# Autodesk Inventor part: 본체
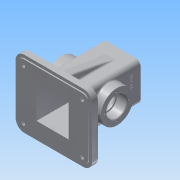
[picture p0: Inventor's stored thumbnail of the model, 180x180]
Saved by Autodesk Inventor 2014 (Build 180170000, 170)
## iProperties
Created: 2015-12
Part Number: 본체
Material: 알루미늄 6061
Document SubType Name: Modeling
Designer: Administrator
Density: 2.71 g/cm^3
Appearance: 알루미늄 - 평지
Author: Administrator
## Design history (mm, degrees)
sketch "스케치1"
  geometry: L1 (32.5, 55)-(-32.5, 55); L2 (-32.5, 55)-(-32.5, -55); L3 (-32.5, -55)-(32.5, -55); L4 (32.5, -55)-(32.5, 55); L5 (32.5, 55)-(-32.5, -55); L6 (-32.5, 55)-(32.5, -55); 1 further point
  constraints: 12 end point, 2 midpoint, 2 parallel, 1 horizontal, 1 perpendicular
  dimensions: "d0" = 65 distance of L3.end L2.end; "d1" = 110 distance of L2.end L1.end
extrude "돌출1" new body sketch "스케치1" stored distance "d2" = 65; taper "d3" = 0 deg
sketch "스케치2"
  geometry: C1 r 20 at (32.5, 32.5); 1 further point
  constraints: 1 centre point, 1 coincident
  dimensions: "d4" = 40 diameter of C1
extrude "돌출2" join sketch "스케치2" distance "d5" = 10; taper "d6" = 0 deg
sketch "스케치3"
  geometry: L1 (50, 27.5)-(-55, 27.5); L2 (-55, 27.5)-(-55, -27.5); L3 (-55, -27.5)-(50, -27.5); L4 (50, -27.5)-(50, 27.5); L5 (-55, -32.5)-(-55, 32.5) reference; 3 further points
  constraints: 8 end point, 3 midpoint, 2 parallel, 1 horizontal, 1 horizontal alignment, 1 perpendicular
  dimensions: "d9" = 105 distance of L3.end L2.end; "d10" = 55 distance of L2.end L1.end
extrude "돌출3" cut sketch "스케치3" stored distance "d11" = 55; taper "d12" = 0 deg
sketch "스케치4"
  geometry: C1 r 20 at (0, 0) reference; C2 r 10.5 at (0, 0)
  constraints: 1 centre point, 1 coincident
  dimensions: "d13" = 21 diameter of C2
extrude "돌출4" cut sketch "스케치4" stored distance "d14" = 55; taper "d15" = 0 deg
sketch "스케치5"
  geometry: C1 r 27.5 at (-32.5, 55); 1 further point
  constraints: 1 centre point, 1 coincident
  dimensions: "d16" = 55 diameter of C1
extrude "돌출5" join sketch "스케치5" distance "d17" = 15; taper "d18" = 0 deg
sketch "스케치6" dims "d19" = 42
  geometry: C1 r 27.5 at (0, 0) reference; 2 further points
  constraints: 1 coincident, 1 vertical alignment, 2 other
hole "구멍1" sketch "스케치6" at (0, 21) diameter "d20" = 3.242; stored, may be unused: countersink angle "d24" = 90 deg, drill point angle "d26" = 118 deg; dims "d21" = 8, "d22" = 4, "d23" = 2, "d25" = 10
sketch "스케치7"
  geometry: C1 r 27.5 at (0, 0) reference; C2 r 17.5 at (0, 0)
  constraints: 1 centre point, 1 coincident
  dimensions: "d30" = 35 diameter of C2
extrude "돌출6" cut sketch "스케치7" distance "d31" = 17; taper "d32" = 0 deg
sketch "스케치8"
  geometry: C1 r 17.5 at (0, 0) reference; C2 r 15 at (0, 0)
  constraints: 1 centre point, 1 coincident
  dimensions: "d33" = 30 diameter of C2
extrude "돌출7" cut sketch "스케치8" stored distance "d34" = 17; taper "d35" = 0 deg
sketch "스케치11" dims "d36" = 29
  geometry: C1 r 20 at (0, 0) reference; 2 further points
  constraints: 1 coincident, 1 vertical alignment, 2 other
hole "구멍2" sketch "스케치11" at (0, 14.5) diameter "d37" = 2.459; stored, may be unused: countersink angle "d41" = 90 deg, drill point angle "d43" = 118 deg; dims "d38" = 8, "d39" = 4, "d40" = 2, "d42" = 10
node "작업 평면1"
sketch "스케치14"
  geometry: L1 (-65, 57.5)-(65, 57.5); L2 (65, 57.5)-(65, -57.5); L3 (65, -57.5)-(-65, -57.5); L4 (-65, -57.5)-(-65, 57.5); L5 (-65, 57.5)-(65, -57.5); L6 (65, 57.5)-(-65, -57.5); 1 further point
  constraints: 12 end point, 2 midpoint, 2 parallel, 1 horizontal, 1 perpendicular
  dimensions: "d50" = 130 distance of L2.end L3.end; "d51" = 115 distance of L1.end L2.end
extrude "돌출8" join sketch "스케치14" distance "d52" = 10; taper "d53" = 0 deg
sketch "스케치15"
  geometry: L1 (60, 52.5)-(-60, 52.5); L2 (-60, 52.5)-(-60, -52.5); L3 (-60, -52.5)-(60, -52.5); L4 (60, -52.5)-(60, 52.5); L5 (60, 52.5)-(-60, -52.5); L6 (-60, 52.5)-(60, -52.5); 1 further point
  constraints: 12 end point, 2 midpoint, 2 parallel, 1 horizontal, 1 perpendicular
  dimensions: "d54" = 120 distance of L3.end L2.end; "d55" = 105 distance of L2.end L1.end
extrude "돌출9" join sketch "스케치15" distance "d56" = 2; taper "d57" = 0 deg
fillet "모깎기1" dims "d59" = 15
sketch "스케치17"
  geometry: C1 r 7.5 at (-50, 42.5); C2 r 7.5 at (50, 42.5); C3 r 7.5 at (-50, -42.5); C4 r 7.5 at (50, -42.5); A1 r 15 centre (-50, 42.5) between (-50, 57.5) and (-65, 42.5) reference; A2 r 15 centre (-50, -42.5) between (-65, -42.5) and (-50, -57.5) reference; A3 r 15 centre (50, -42.5) between (50, -57.5) and (65, -42.5) reference; A4 r 15 centre (50, 42.5) between (65, 42.5) and (50, 57.5) reference; 1 further point
  constraints: 4 centre point, 4 coincident
  dimensions: "d60" = 15 diameter of C1; "d61" = 15 diameter of C2; "d62" = 15 diameter of C3; "d63" = 15 diameter of C4
extrude "돌출10" join sketch "스케치17" distance "d64" = 3; taper "d65" = 0 deg
sketch "스케치18"
  geometry: C1 r 7.5 at (0, 0) reference; C2 r 3 at (0, 0); 1 further point
  constraints: 1 centre point, 1 coincident
  dimensions: "d66" = 6 diameter of C2
extrude "돌출11" cut sketch "스케치18" stored distance "d67" = 3; taper "d68" = 0 deg
sketch "스케치19"
  geometry: C1 r 7.5 at (0, 0) reference; C2 r 3 at (0, 0); 1 further point
  constraints: 1 centre point, 1 coincident
  dimensions: "d69" = 6 diameter of C2
extrude "돌출12" cut sketch "스케치19" stored distance "d70" = 3; taper "d71" = 0 deg
sketch "스케치21"
  geometry: L1 (65, -20)-(55, -20) reference; L2 (55, -20)-(55, -32.5) reference; L3 (55, -32.5)-(-50, -32.5) reference; L4 (-50, -32.5)-(-50, -57.5) reference; L5 (-50, -57.5)-(-60, -57.5) reference; L6 (-60, -57.5)-(-60, -52.5) reference; L7 (-60, -52.5)-(-62, -52.5) reference; L8 (-62, -52.5)-(-62, 52.5) reference; L9 (-62, 52.5)-(-60, 52.5) reference; L10 (-60, 52.5)-(-60, 57.5) reference; L11 (-60, 57.5)-(-50, 57.5) reference; L12 (-50, 57.5)-(-50, 32.5) reference; L13 (-50, 32.5)-(55, 32.5) reference; L14 (55, 32.5)-(55, 20) reference; L15 (55, 20)-(65, 20) reference; L16 (65, 20)-(65, 15.73) reference; L17 (65, 15.73)-(55, 15.73) reference; L18 (55, 15.73)-(54.261, 14.5) reference; L19 (54.261, 14.5)-(55, 13.271) reference; L20 (55, 13.271)-(65, 13.271) reference; L21 (65, 13.271)-(65, 10.5) reference; L22 (65, 10.5)-(50, 10.5) reference; L23 (50, 10.5)-(50, 27.5) reference; L24 (50, 27.5)-(-50, 27.5) reference; L25 (-50, 27.5)-(-50, -27.5) reference; L26 (-50, -27.5)-(50, -27.5) reference; L27 (50, -27.5)-(50, -10.5) reference; L28 (50, -10.5)-(65, -10.5) reference; L29 (65, -10.5)-(65, -13.271) reference; L30 (65, -13.271)-(55, -13.271) reference; L31 (55, -13.271)-(54.261, -14.5) reference; L32 (54.261, -14.5)-(55, -15.73) reference; L33 (55, -15.73)-(65, -15.73) reference; L34 (65, -15.73)-(65, -20) reference; L35 (-50, 57.5)-(-50, 47.5); L36 (-50, 47.5)-(35.069, 32.5); 1 further point
  constraints: 4 end point, 2 point on line
  dimensions: "d77" = 10 distance of L11.end L35.end; "d78" = 80 deg angle of L12 L36
extrude "돌출13" join sketch "스케치21" stored distance "d79" = 15; taper "d80" = 0 deg
fillet "모깎기2" dims "d81" = 10
sketch "스케치22"
  geometry: L1 (-37.5, -22.621)-(-36.526, -21) reference; L2 (-36.526, -21)-(-37.5, -19.379) reference; L3 (-37.5, -19.379)-(-47.5, -19.379) reference; L4 (-47.5, -19.379)-(-47.5, -17.5) reference; L5 (-47.5, -17.5)-(-30.5, -17.5) reference; L6 (-30.5, -17.5)-(-30.5, -15) reference; L7 (-30.5, -15)-(-27.5, -15) reference; L8 (-27.5, -15)-(-27.5, -50) reference; L9 (-27.5, -50)-(27.5, -50) reference; L10 (27.5, -50)-(27.5, -15) reference; L11 (27.5, -15)-(30.5, -15) reference; L12 (30.5, -15)-(30.5, -17.5) reference; L13 (30.5, -17.5)-(47.5, -17.5) reference; L14 (47.5, -17.5)-(47.5, -19.379) reference; L15 (47.5, -19.379)-(37.5, -19.379) reference; L16 (37.5, -19.379)-(36.526, -21) reference; L17 (36.526, -21)-(37.5, -22.621) reference; L18 (37.5, -22.621)-(47.5, -22.621) reference; L19 (47.5, -22.621)-(47.5, -27.5) reference; L20 (47.5, -27.5)-(32.5, -27.5) reference; L21 (32.5, -27.5)-(32.5, -50) reference; L22 (32.5, -50)-(65, -50) reference; L23 (65, -50)-(65, -60) reference; L24 (65, -60)-(60, -60) reference; L25 (60, -60)-(60, -62) reference; L26 (60, -62)-(-60, -62) reference; L27 (-60, -62)-(-60, -60) reference; L28 (-60, -60)-(-65, -60) reference; L29 (-65, -60)-(-65, -50) reference; L30 (-65, -50)-(-32.5, -50) reference; L31 (-32.5, -50)-(-32.5, -27.5) reference; L32 (-32.5, -27.5)-(-47.5, -27.5) reference; L33 (-47.5, -27.5)-(-47.5, -22.621) reference; L34 (-47.5, -22.621)-(-37.5, -22.621) reference; L35 (-20, 55)-(-20, 65) reference; L36 (-20, 65)-(-15.729, 65) reference; L37 (-15.729, 65)-(-15.729, 55) reference; L38 (-15.729, 55)-(-14.5, 54.261) reference; L39 (-14.5, 54.261)-(-13.27, 55) reference; L40 (-13.27, 55)-(-13.27, 65) reference; L41 (-13.27, 65)-(-10.5, 65) reference; L42 (-10.5, 65)-(-10.5, 50) reference; L43 (-10.5, 50)-(-27.5, 50) reference; L44 (-27.5, 50)-(-27.5, 15) reference; L45 (-27.5, 15)-(-30.5, 15) reference; L46 (-30.5, 15)-(-30.5, 17.5) reference; L47 (-30.5, 17.5)-(-47.5, 17.5) reference; L48 (-47.5, 17.5)-(-47.5, 19.379) reference; L49 (-47.5, 19.379)-(-37.5, 19.379) reference; L50 (-37.5, 19.379)-(-36.526, 21) reference; L51 (-36.526, 21)-(-37.5, 22.621) reference; L52 (-37.5, 22.621)-(-47.5, 22.621) reference; L53 (-47.5, 22.621)-(-47.5, 27.5) reference; L54 (-47.5, 27.5)-(-32.5, 27.5) reference; L55 (-32.5, 27.5)-(-32.5, 55) reference; L56 (-32.5, 55)-(-20, 55) reference; L57 (20, 65)-(20, 55) reference; L58 (20, 55)-(32.5, 55) reference; L59 (32.5, 55)-(32.5, 27.5) reference; L60 (32.5, 27.5)-(47.5, 27.5) reference; L61 (47.5, 27.5)-(47.5, 22.621) reference; L62 (47.5, 22.621)-(37.5, 22.621) reference; L63 (37.5, 22.621)-(36.526, 21) reference; L64 (36.526, 21)-(37.5, 19.379) reference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; 2 further points
  constraints: 10 end point, 3 perpendicular, 2 point on line, 1 parallel
  dimensions: "d82" = 10 distance of L21.end L79.end; "d108" = 34.5 distance between parallel lines of L23 L82; "d109" = 34.46005 distance between parallel lines of L24 L81; "d110" = 27.5 distance from line of point (37.5, -27.5) L23
  node "절단 모서리 투영3"
fillet "모깎기7" dims "d93" = 3
sketch "스케치23"
  geometry: L1 (-27.5, 27.5)-(27.5, 27.5); L2 (27.5, 27.5)-(27.5, -27.5); L3 (27.5, -27.5)-(-27.5, -27.5); L4 (-27.5, -27.5)-(-27.5, 27.5); L5 (-27.5, 27.5)-(27.5, -27.5); L6 (27.5, 27.5)-(-27.5, -27.5); 1 further point
  constraints: 12 end point, 2 midpoint, 2 parallel, 1 horizontal, 1 perpendicular
  dimensions: "d98" = 55 distance of L2.end L3.end; "d99" = 55 distance of L1.end L2.end
extrude "돌출16" cut sketch "스케치23" stored distance "d100" = 5; taper "d101" = 0 deg
fillet "모깎기14" dims "d104" = 8
fillet "모깎기15" dims "d105" = 0.3
fillet "모깎기16" dims "d106" = 3
fillet "모깎기17" dims "d107" = 3
extrude "돌출17" join sketch "스케치22" stored distance "d111" = 6; taper "d112" = 0 deg
fillet "모깎기18" dims "d113" = 3
fillet "모깎기19" dims "d114" = 3
fillet "모깎기20" dims "d115" = 3
fillet "모깎기21" dims "d116" = 3
sketch "스케치24"
  geometry: L1 (77, -117)-(-28, -117) reference; L2 (-28, -117)-(-28, -115) reference; L3 (-28, -115)-(-33, -115) reference; L4 (-33, -115)-(-33, -105) reference; L5 (-33, -105)-(-7.55, -105) reference; L6 (18.5, -102)-(0, -102) reference; L7 (18.5, -84.904)-(18.5, -102) reference; L8 (0, -102)-(0, -73.166) reference; L9 (77, -115)-(77, -117) reference; L10 (82, -115)-(77, -115) reference; L11 (82, -105)-(82, -115) reference; L12 (56.55, -105)-(82, -105) reference; L13 (49, -73.166)-(49, -102) reference; L14 (30.5, -102)-(30.5, -84.904) reference; L15 (49, -102)-(30.5, -102) reference; L16 (49, 0)-(49, -36.834) reference; L17 (0, 0)-(49, 0) reference; L18 (0, -36.834)-(0, 0) reference; L19 (-8, 0)-(-8, -102) reference; L20 (44.5, 10)-(4.5, 10) reference; C1 r 17.5 at (24.5, -55) reference; A1 r 30.5 centre (24.5, -55) between (0, -73.166) and (18.5, -84.904) reference; A2 r 30.5 centre (24.5, -55) between (30.5, -84.904) and (49, -73.166) reference; A3 r 30.5 centre (24.5, -55) between (49, -36.834) and (0, -36.834) reference; 1 further point
  constraints: 2 vertical alignment, 3 other
  dimensions: "d117" = 32.5 distance from line of L19 point (24.5, -16); "d118" = 26 distance from line of L20 point (24.5, -16)
feature "엠보싱1" sketch "스케치24" dims "d119" = 0.5, "d120" = 0
chamfer "모따기1" distance "d121" = 1; stored, may be unused: second distance "d122" = 2, angle "d123" = 45 deg
node "솔리드1"
pattern_circular "원형 패턴1" dims angle "d28" = 360 deg
pattern_circular "원형 패턴2" dims angle "d45" = 360 deg
mirror "대칭1"
mirror "대칭2"
mirror "대칭3"
mirror "대칭5"
node "절단 모서리 투영2"
node "절단 모서리 투영4"
